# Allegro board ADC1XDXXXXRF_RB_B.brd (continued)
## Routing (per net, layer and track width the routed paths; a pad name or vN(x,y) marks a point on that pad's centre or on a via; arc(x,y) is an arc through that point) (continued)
FMC_DQD-7: length 142.1
  TOP w0.102: v1(119.71,97.74) U5.G7
  SIG3 w0.102: v1(119.71,97.74) 119.71,97.97 119.53,98.14 81.91,98.14 76.89,93.12 v3(76.89,92.79)
  BOTTOM w0.102: v3(76.89,92.79) 76.68,92.99 76.68,93.43 76.03,94.08 75.15,94.08 72.29,91.22 72.29,83.54 71.91,83.16 67.84,83.16 67.54,83.46 67.54,93.32 66.04,94.82 55.55,94.82 53.62,92.89 16.2,92.89 15.72,92.41 15.72,91.95 15.44,91.67 14.96,91.67 14.48,91.19 14.48,87.91 14.83,87.55 15.44,87.55 15.75,87.25 15.75,82.85 15.65,82.75 14.48,82.75 FMC.F11
FMC_DQD-8: length 142.1
  TOP w0.102: v1(118.71,101.75) 119.22,101.24 U5.D6
  SIG3 w0.102: v3(12.06,82.63) 12.6,82.09 46.27,82.09 46.38,82.19 46.38,82.53 46.6,82.75 46.97,82.75 47.19,82.53 47.19,82.19 47.29,82.09 47.49,82.09 47.59,82.19 47.59,82.53 47.81,82.75 48.19,82.75 48.41,82.53 48.41,82.19 48.51,82.09 48.71,82.09 48.81,82.19 48.81,82.53 49.03,82.75 49.41,82.75 49.63,82.53 49.63,82.19 49.73,82.09 49.93,82.09 50.03,82.19 50.03,82.53 50.25,82.75 50.62,82.75 50.85,82.53 50.85,82.19 50.95,82.09 51.15,82.09 51.25,82.19 51.25,82.53 51.47,82.75 51.84,82.75 52.06,82.53 52.06,82.19 52.17,82.09 52.37,82.09 52.47,82.19 52.47,82.53 52.69,82.75 53.06,82.75 53.28,82.53 53.28,82.19 53.39,82.09 53.59,82.09 53.69,82.19 53.69,82.53 53.91,82.75 54.28,82.75 54.5,82.53 54.5,82.19 54.6,82.09 54.81,82.09 54.91,82.19 54.91,82.53 55.13,82.75 55.5,82.75 55.72,82.53 55.72,82.19 55.82,82.09 56.03,82.09 56.13,82.19 56.13,82.53 56.35,82.75 56.72,82.75 56.94,82.53 56.94,82.19 57.04,82.09 57.25,82.09 57.35,82.19 57.35,82.53 57.57,82.75 57.94,82.75 58.16,82.53 58.16,82.19 58.26,82.09 58.47,82.09 58.57,82.19 58.57,82.53 58.79,82.75 59.16,82.75 59.38,82.53 59.38,82.19 59.48,82.09 59.68,82.09 59.79,82.19 59.79,82.56 60.01,82.78 60.38,82.78 60.6,82.56 60.6,82.19 60.7,82.09 61.16,82.09 69.6,90.53 69.6,91.74 69.49,91.84 69.16,91.84 68.94,92.06 68.94,92.43 69.16,92.65 69.49,92.65 69.6,92.75 69.6,92.96 69.49,93.06 69.16,93.06 68.94,93.28 68.94,93.65 69.16,93.87 69.49,93.87 69.6,93.97 69.6,94.17 69.49,94.28 69.16,94.28 68.94,94.5 68.94,94.87 69.16,95.09 69.49,95.09 69.6,95.19 69.6,95.39 69.49,95.5 69.16,95.5 68.94,95.72 68.94,96.09 69.16,96.31 69.49,96.31 69.6,96.41 69.6,96.61 69.49,96.71 69.16,96.71 68.94,96.94 68.94,97.31 69.16,97.53 69.49,97.53 69.6,97.63 69.6,97.83 69.49,97.93 69.16,97.93 68.94,98.15 68.94,98.53 69.16,98.75 69.49,98.75 69.6,98.85 69.6,99.05 69.49,99.15 69.16,99.15 68.94,99.37 68.94,99.75 69.16,99.97 69.49,99.97 69.6,100.07 69.6,101.25 69.89,101.55 112.98,101.55 113.17,101.36 119.04,101.36 119.2,101.52 119.2,101.6 119.05,101.75 118.71,101.75 v1(118.71,101.75)
  BOTTOM w0.102: FMC.E10 v3(12.06,82.63)
FMC_DQD-9: length 142.1
  TOP w0.102: U5.A5 v1(118.71,104.76)
  SIG3 w0.102: v3(63.02,91.52) 63.02,91.53 63.25,91.76 63.25,93.14 63.14,93.24 60.7,93.24 60.48,93.46 60.48,93.83 60.7,94.05 63.14,94.05 63.25,94.15 63.25,94.36 63.14,94.46 60.7,94.46 60.48,94.68 60.48,95.05 60.7,95.27 63.14,95.27 63.25,95.37 63.25,95.57 63.14,95.68 60.7,95.68 60.48,95.9 60.48,96.27 60.7,96.49 63.14,96.49 63.25,96.59 63.25,96.79 63.14,96.9 60.7,96.9 60.48,97.12 60.48,97.49 60.7,97.71 63.14,97.71 63.25,97.81 63.25,106.87 64.28,107.9 116.47,107.9 118.31,106.06 118.31,104.63 118.43,104.5 118.58,104.5 118.71,104.63 v1(118.71,104.76)
  BOTTOM w0.102: FMC.K14 19.05,86.66 19.15,86.56 52.7,86.56 57.15,91.01 63.12,91.01 63.22,91.11 63.22,91.31 v3(63.02,91.52)
FMC_DQD-10: length 142.2
  TOP w0.102: v1(116.71,103.76) 117.22,103.25 U5.B4
  SIG3 w0.102: v1(116.71,103.76) 117.31,104.36 117.31,105 115.68,106.63 65.04,106.63 64.52,106.1 64.52,91.14 59.28,85.9 53.39,85.9 53.28,86 53.28,87.43 53.06,87.66 52.69,87.66 52.47,87.43 52.47,86 52.37,85.9 52.17,85.9 52.06,86 52.06,87.43 51.84,87.66 51.47,87.66 51.25,87.43 51.25,86 51.15,85.9 50.95,85.9 50.85,86 50.85,87.43 50.62,87.66 50.25,87.66 50.03,87.43 50.03,86 49.93,85.9 49.73,85.9 49.63,86 49.63,87.43 49.41,87.66 49.03,87.66 48.81,87.43 48.81,86 48.71,85.9 48.51,85.9 48.41,86 48.41,87.43 48.19,87.66 47.81,87.66 47.59,87.43 47.59,86 47.49,85.9 47.29,85.9 47.19,86 47.19,87.43 46.97,87.66 46.6,87.66 46.38,87.43 46.38,86 46.27,85.9 46.07,85.9 45.97,86 45.97,87.43 45.75,87.66 45.38,87.66 45.16,87.43 45.16,86 45.05,85.9 18.95,85.9 v3(18.41,86.44)
  BOTTOM w0.102: FMC.J13 v3(18.41,86.44)
FMC_DQD-11: length 142.1
  TOP w0.102: v1(115.7,103.76) 116.22,103.25 U5.B3
  SIG3 w0.102: v1(115.7,103.76) 115.31,104.16 114.61,104.16 113.61,105.16 66.42,105.16 65.99,104.72 65.99,99.98 65.77,99.76 65.46,99.76 65.35,99.66 65.35,99.46 65.46,99.36 65.77,99.36 65.99,99.14 65.99,98.76 65.77,98.54 65.46,98.54 65.35,98.44 65.35,98.24 65.46,98.14 65.77,98.14 65.99,97.92 65.99,97.54 65.77,97.32 65.46,97.32 65.35,97.22 65.35,97.02 65.46,96.92 65.77,96.92 65.99,96.7 65.99,96.33 65.77,96.1 65.46,96.1 65.35,96 65.35,95.8 65.46,95.7 65.77,95.7 65.99,95.48 65.99,95.11 65.77,94.89 65.46,94.89 65.35,94.78 65.35,94.58 65.46,94.48 65.77,94.48 65.99,94.26 65.99,93.89 65.77,93.67 65.46,93.67 65.35,93.56 65.35,93.36 65.46,93.26 65.77,93.26 65.99,93.04 65.99,90.91 59.51,84.43 58.18,84.43 57.96,84.65 57.96,84.96 57.86,85.06 57.65,85.06 57.55,84.96 57.55,84.65 57.33,84.43 56.96,84.43 56.74,84.65 56.74,84.96 56.64,85.06 56.43,85.06 56.33,84.96 56.33,84.65 56.11,84.43 55.74,84.43 55.52,84.65 55.52,84.96 55.42,85.06 55.21,85.06 55.11,84.96 55.11,84.65 54.89,84.43 54.52,84.43 54.3,84.65 54.3,84.96 54.2,85.06 54,85.06 53.89,84.96 53.89,84.65 53.67,84.43 53.3,84.43 53.08,84.65 53.08,84.96 52.98,85.06 52.78,85.06 52.67,84.96 52.67,84.65 52.45,84.43 52.08,84.43 51.86,84.65 51.86,84.96 51.76,85.06 51.56,85.06 51.46,84.96 51.46,84.65 51.23,84.43 50.86,84.43 50.64,84.65 50.64,84.99 50.54,85.09 50.34,85.09 50.24,84.99 50.24,84.65 50.02,84.43 49.64,84.43 49.42,84.65 49.42,84.99 49.32,85.09 49.12,85.09 49.02,84.99 49.02,84.65 48.8,84.43 48.42,84.43 48.2,84.65 48.2,84.99 48.1,85.09 47.9,85.09 47.8,84.99 47.8,84.65 47.58,84.43 47.21,84.43 46.98,84.65 46.98,84.99 46.88,85.09 46.68,85.09 46.58,84.99 46.58,84.65 46.36,84.43 46,84.43 45.52,84.91 19.35,84.91 18.87,84.43 16.37,84.43 15.12,85.69 11.52,85.69 11.33,85.88 11.33,86.94 11.56,87.17 12.8,87.17 v3(13.34,87.71)
  BOTTOM w0.102: FMC.F14 v3(13.34,87.71)
FMC_ORI+: length 142.1
  TOP w0.102: v1(119.72,95.75) U5.J7
  SIG1 w0.102: v1(119.72,95.75) 119.32,96.14 119.32,99 117.97,100.36 115.27,100.36 103.06,112.57 55.59,112.57 55.49,112.67 55.49,113.9 55.27,114.12 54.9,114.12 54.68,113.9 54.68,112.67 54.58,112.57 54.38,112.57 54.27,112.67 54.27,113.9 54.05,114.12 53.68,114.12 53.46,113.9 53.46,112.67 53.36,112.57 53.16,112.57 53.05,112.67 53.05,113.9 52.83,114.12 52.46,114.12 52.24,113.9 52.24,112.67 52.14,112.57 51.94,112.57 51.84,112.67 51.84,113.93 51.62,114.15 51.24,114.15 51.02,113.93 51.02,112.67 50.92,112.57 50.72,112.57 50.62,112.67 50.62,113.93 50.4,114.15 50.02,114.15 49.8,113.93 49.8,112.67 49.7,112.57 49.5,112.57 49.4,112.67 49.4,113.93 49.18,114.15 48.8,114.15 48.58,113.93 48.58,112.67 48.48,112.57 48.28,112.57 48.18,112.67 48.18,113.93 47.96,114.15 47.59,114.15 47.37,113.93 47.37,112.67 47.26,112.57 47.06,112.57 46.96,112.67 46.96,113.93 46.74,114.15 46.37,114.15 46.15,113.93 46.15,112.67 46.04,112.57 14.22,112.57 14.07,112.73 14.07,113.48 14.23,113.64 16.61,113.64 v3(17.14,113.11)
  BOTTOM w0.102: FMC.H34 v3(17.14,113.11)
FMC_ORI-: length 142.1
  TOP w0.102: v1(118.72,95.75) U5.J6
  SIG1 w0.102: v1(118.72,95.75) 119.11,96.14 119.11,98.92 117.88,100.15 115.19,100.15 102.97,112.37 55.51,112.37 55.29,112.59 55.29,113.82 55.19,113.92 54.99,113.92 54.88,113.82 54.88,112.59 54.66,112.37 54.29,112.37 54.07,112.59 54.07,113.82 53.97,113.92 53.77,113.92 53.66,113.82 53.66,112.59 53.44,112.37 53.07,112.37 52.85,112.59 52.85,113.82 52.75,113.92 52.55,113.92 52.45,113.82 52.45,112.59 52.22,112.37 51.85,112.37 51.63,112.59 51.63,113.84 51.53,113.94 51.33,113.94 51.23,113.84 51.23,112.59 51.01,112.37 50.63,112.37 50.41,112.59 50.41,113.84 50.31,113.94 50.11,113.94 50.01,113.84 50.01,112.59 49.79,112.37 49.41,112.37 49.19,112.59 49.19,113.84 49.09,113.94 48.89,113.94 48.79,113.84 48.79,112.59 48.57,112.37 48.2,112.37 47.97,112.59 47.97,113.84 47.87,113.94 47.67,113.94 47.57,113.84 47.57,112.59 47.35,112.37 46.98,112.37 46.76,112.59 46.76,113.84 46.65,113.94 46.45,113.94 46.35,113.84 46.35,112.59 46.13,112.37 14.14,112.37 13.87,112.64 13.87,113.56 14.15,113.84 16.1,113.84 16.28,114.02 16.28,114.25 16.15,114.38 v3(15.88,114.38)
  BOTTOM w0.102: FMC.H35 v3(15.88,114.38)
FMC_ORQ+: length 142.1
  TOP w0.102: v1(120.71,96.74) U5.H8
  SIG1 w0.102: v1(120.71,96.74) 120.31,96.34 120.31,95.41 120.04,95.14 118.34,95.14 118.12,95.36 118.12,98.96 117.93,99.14 112.29,99.14 100.33,111.1 71.36,111.1 71.14,111.32 71.14,111.66 71.04,111.76 70.83,111.76 70.73,111.66 70.73,111.32 70.51,111.1 70.14,111.1 69.92,111.32 69.92,111.66 69.82,111.76 69.62,111.76 69.51,111.66 69.51,111.32 69.29,111.1 68.92,111.1 68.7,111.32 68.7,111.66 68.6,111.76 68.4,111.76 68.29,111.66 68.29,111.32 68.07,111.1 67.7,111.1 67.48,111.32 67.48,111.66 67.38,111.76 67.18,111.76 67.08,111.66 67.08,111.32 66.86,111.1 66.48,111.1 66.26,111.32 66.26,111.66 66.16,111.76 65.96,111.76 65.86,111.66 65.86,111.32 65.64,111.1 65.26,111.1 65.04,111.32 65.04,111.66 64.94,111.76 64.74,111.76 64.64,111.66 64.64,111.32 64.42,111.1 64.04,111.1 63.82,111.32 63.82,111.66 63.72,111.76 63.52,111.76 63.42,111.66 63.42,111.32 63.2,111.1 62.83,111.1 62.61,111.32 62.61,111.66 62.5,111.76 62.3,111.76 62.2,111.66 62.2,111.32 61.98,111.1 61.61,111.1 61.39,111.32 61.39,111.66 61.28,111.76 61.08,111.76 60.98,111.66 60.98,111.32 60.76,111.1 60.39,111.1 60.17,111.32 60.17,111.66 60.07,111.76 59.86,111.76 59.76,111.66 59.76,111.32 59.54,111.1 59.17,111.1 58.95,111.32 58.95,111.66 58.85,111.76 58.64,111.76 58.54,111.66 58.54,111.32 58.32,111.1 57.95,111.1 57.73,111.32 57.73,111.66 57.63,111.76 57.42,111.76 57.32,111.66 57.32,111.32 57.1,111.1 56.73,111.1 56.51,111.32 56.51,111.66 56.41,111.76 56.2,111.76 56.1,111.66 56.1,111.32 55.88,111.1 55.51,111.1 55.29,111.32 55.29,111.63 55.19,111.73 54.99,111.73 54.88,111.63 54.88,111.32 54.66,111.1 54.29,111.1 54.07,111.32 54.07,111.63 53.97,111.73 53.77,111.73 53.66,111.63 53.66,111.32 53.44,111.1 53.07,111.1 52.85,111.32 52.85,111.63 52.75,111.73 52.55,111.73 52.45,111.63 52.45,111.32 52.22,111.1 51.85,111.1 51.63,111.32 51.63,111.63 51.53,111.73 51.33,111.73 51.23,111.63 51.23,111.32 51.01,111.1 50.63,111.1 50.41,111.32 50.41,111.63 50.31,111.73 50.11,111.73 50.01,111.63 50.01,111.32 49.79,111.1 49.41,111.1 49.19,111.32 49.19,111.63 49.09,111.73 48.89,111.73 48.79,111.63 48.79,111.32 48.57,111.1 48.2,111.1 47.97,111.32 47.97,111.63 47.87,111.73 47.67,111.73 47.57,111.63 47.57,111.32 47.35,111.1 46.98,111.1 46.76,111.32 46.76,111.63 46.65,111.73 46.45,111.73 46.35,111.63 46.35,111.32 46.13,111.1 15.49,111.1 15.34,110.95 15.34,108.81 15.09,108.56 12.6,108.56 v3(12.06,108.03)
  BOTTOM w0.102: FMC.E30 v3(12.06,108.03)
FMC_ORQ-: length 142.1
  TOP w0.102: v1(119.71,96.74) U5.H7
  SIG1 w0.102: v3(12.06,109.3) 12.06,108.92 12.22,108.76 15,108.76 15.14,108.9 15.14,111.03 15.41,111.3 46.04,111.3 46.15,111.4 46.15,111.72 46.37,111.94 46.74,111.94 46.96,111.72 46.96,111.4 47.06,111.3 47.26,111.3 47.37,111.4 47.37,111.72 47.59,111.94 47.96,111.94 48.18,111.72 48.18,111.4 48.28,111.3 48.48,111.3 48.58,111.4 48.58,111.72 48.8,111.94 49.18,111.94 49.4,111.72 49.4,111.4 49.5,111.3 49.7,111.3 49.8,111.4 49.8,111.72 50.02,111.94 50.4,111.94 50.62,111.72 50.62,111.4 50.72,111.3 50.92,111.3 51.02,111.4 51.02,111.72 51.24,111.94 51.62,111.94 51.84,111.72 51.84,111.4 51.94,111.3 52.14,111.3 52.24,111.4 52.24,111.72 52.46,111.94 52.83,111.94 53.05,111.72 53.05,111.4 53.16,111.3 53.36,111.3 53.46,111.4 53.46,111.72 53.68,111.94 54.05,111.94 54.27,111.72 54.27,111.4 54.38,111.3 54.58,111.3 54.68,111.4 54.68,111.72 54.9,111.94 55.27,111.94 55.49,111.72 55.49,111.4 55.59,111.3 55.8,111.3 55.9,111.4 55.9,111.74 56.12,111.96 56.49,111.96 56.71,111.74 56.71,111.4 56.81,111.3 57.02,111.3 57.12,111.4 57.12,111.74 57.34,111.96 57.71,111.96 57.93,111.74 57.93,111.4 58.03,111.3 58.24,111.3 58.34,111.4 58.34,111.74 58.56,111.96 58.93,111.96 59.15,111.74 59.15,111.4 59.25,111.3 59.46,111.3 59.56,111.4 59.56,111.74 59.78,111.96 60.15,111.96 60.37,111.74 60.37,111.4 60.47,111.3 60.67,111.3 60.78,111.4 60.78,111.74 61,111.96 61.37,111.96 61.59,111.74 61.59,111.4 61.69,111.3 61.89,111.3 62,111.4 62,111.74 62.22,111.96 62.59,111.96 62.81,111.74 62.81,111.4 62.91,111.3 63.11,111.3 63.21,111.4 63.21,111.74 63.44,111.96 63.81,111.96 64.03,111.74 64.03,111.4 64.13,111.3 64.33,111.3 64.43,111.4 64.43,111.74 64.65,111.96 65.03,111.96 65.25,111.74 65.25,111.4 65.35,111.3 65.55,111.3 65.65,111.4 65.65,111.74 65.87,111.96 66.25,111.96 66.47,111.74 66.47,111.4 66.57,111.3 66.77,111.3 66.87,111.4 66.87,111.74 67.09,111.96 67.46,111.96 67.69,111.74 67.69,111.4 67.79,111.3 67.99,111.3 68.09,111.4 68.09,111.74 68.31,111.96 68.68,111.96 68.9,111.74 68.9,111.4 69.01,111.3 69.21,111.3 69.31,111.4 69.31,111.74 69.53,111.96 69.9,111.96 70.12,111.74 70.12,111.4 70.23,111.3 70.43,111.3 70.53,111.4 70.53,111.74 70.75,111.96 71.12,111.96 71.34,111.74 71.34,111.4 71.44,111.3 100.41,111.3 112.37,99.34 118.02,99.34 118.32,99.04 118.32,95.45 118.42,95.34 119.96,95.34 120.11,95.5 120.11,96.5 119.87,96.74 v1(119.71,96.74)
  BOTTOM w0.102: FMC.E31 v3(12.06,109.3)
FMC_PG_C2M: length 124.3
  TOP w0.102: U5.R5 118.2,90.24 v1(117.71,89.75)
  BOTTOM w0.152: FMC.D1 12.67,69.32 47.75,69.32 J155.1 50.72,66.34 76.83,66.34 84.02,73.53 84.02,82.75 90.47,89.2 109.42,89.2 R155.2 110.46,90.25 117.21,90.25 v1(117.71,89.75)
FMC_PG_M2C: length 123.5
  TOP w0.102: v1(118.71,89.75) 119.2,90.24 U5.R6
  BOTTOM w0.152: v1(118.71,89.75) 118.21,90.24 118.21,91.03 118.01,91.24 110.26,91.24 R156.1 109.55,91.24 90.35,91.24 83.24,84.12 83.24,74.5 76.35,67.61 J156.1 50.09,69.93 14.61,69.93 FMC.F1
FMC_RCOUT1+: length 142.1
  TOP w0.102: U5.U23 v1(135.72,87.74)
  SIG1 w0.102: v1(135.72,87.74) 135.72,87.32 136.12,86.92 136.12,86.57 135.69,86.14 131.48,86.14 130.48,87.14 119.53,87.14 119.31,86.92 119.31,86.43 119.02,86.14 101.95,86.14 94.77,93.32 62.85,93.32 62.63,93.54 62.63,93.73 62.53,93.83 62.33,93.83 62.22,93.73 62.22,93.54 62,93.32 61.63,93.32 61.41,93.54 61.41,93.73 61.31,93.83 61.11,93.83 61,93.73 61,93.54 60.78,93.32 60.41,93.32 60.19,93.54 60.19,93.73 60.09,93.83 59.89,93.83 59.79,93.73 59.79,93.54 59.57,93.32 59.19,93.32 58.97,93.54 58.97,93.73 58.87,93.83 58.67,93.83 58.57,93.73 58.57,93.54 58.35,93.32 57.97,93.32 57.75,93.54 57.75,93.73 57.65,93.83 57.45,93.83 57.35,93.73 57.35,93.54 57.13,93.32 56.76,93.32 56.53,93.54 56.53,93.73 56.43,93.83 56.23,93.83 56.13,93.73 56.13,93.54 55.91,93.32 55.54,93.32 55.32,93.54 55.32,93.73 55.21,93.83 55.01,93.83 54.91,93.73 54.91,93.54 54.69,93.32 54.32,93.32 54.1,93.54 54.1,93.75 53.99,93.85 53.79,93.85 53.69,93.75 53.69,93.54 53.47,93.32 53.1,93.32 52.88,93.54 52.88,93.75 52.78,93.85 52.57,93.85 52.47,93.75 52.47,93.54 52.25,93.32 51.88,93.32 51.66,93.54 51.66,93.75 51.56,93.85 51.35,93.85 51.25,93.75 51.25,93.54 51.03,93.32 50.66,93.32 50.44,93.54 50.44,93.75 50.34,93.85 50.13,93.85 50.03,93.75 50.03,93.54 49.81,93.32 49.44,93.32 49.22,93.54 49.22,93.75 49.12,93.85 48.91,93.85 48.81,93.75 48.81,93.54 48.59,93.32 48.22,93.32 48,93.54 48,93.75 47.9,93.85 47.7,93.85 47.59,93.75 47.59,93.54 47.37,93.32 47,93.32 46.78,93.54 46.78,93.75 46.68,93.85 46.48,93.85 46.37,93.75 46.37,93.54 46.15,93.32 11.33,93.32 v3(10.79,92.79)
  BOTTOM w0.102: FMC.C18 v3(10.79,92.79)
FMC_RCOUT1-: length 142
  TOP w0.102: U5.V23 v1(135.72,86.74)
  SIG1 w0.102: v3(9.53,94.06) 9.47,94.01 9.47,93.65 9.6,93.52 46.07,93.52 46.17,93.62 46.17,93.84 46.39,94.06 46.76,94.06 46.98,93.84 46.98,93.62 47.09,93.52 47.29,93.52 47.39,93.62 47.39,93.84 47.61,94.06 47.98,94.06 48.2,93.84 48.2,93.62 48.3,93.52 48.51,93.52 48.61,93.62 48.61,93.84 48.83,94.06 49.2,94.06 49.42,93.84 49.42,93.62 49.52,93.52 49.73,93.52 49.83,93.62 49.83,93.84 50.05,94.06 50.42,94.06 50.64,93.84 50.64,93.62 50.74,93.52 50.95,93.52 51.05,93.62 51.05,93.84 51.27,94.06 51.64,94.06 51.86,93.84 51.86,93.62 51.96,93.52 52.17,93.52 52.27,93.62 52.27,93.84 52.49,94.06 52.86,94.06 53.08,93.84 53.08,93.62 53.18,93.52 53.38,93.52 53.49,93.62 53.49,93.84 53.71,94.06 54.08,94.06 54.3,93.84 54.3,93.62 54.4,93.52 54.6,93.52 54.71,93.62 54.71,93.81 54.93,94.03 55.3,94.03 55.52,93.81 55.52,93.62 55.62,93.52 55.82,93.52 55.92,93.62 55.92,93.81 56.15,94.03 56.52,94.03 56.74,93.81 56.74,93.62 56.84,93.52 57.04,93.52 57.14,93.62 57.14,93.81 57.36,94.03 57.74,94.03 57.96,93.81 57.96,93.62 58.06,93.52 58.26,93.52 58.36,93.62 58.36,93.81 58.58,94.03 58.96,94.03 59.18,93.81 59.18,93.62 59.28,93.52 59.48,93.52 59.58,93.62 59.58,93.81 59.8,94.03 60.17,94.03 60.4,93.81 60.4,93.62 60.5,93.52 60.7,93.52 60.8,93.62 60.8,93.81 61.02,94.03 61.39,94.03 61.61,93.81 61.61,93.62 61.72,93.52 61.92,93.52 62.02,93.62 62.02,93.81 62.24,94.03 62.61,94.03 62.83,93.81 62.83,93.62 62.94,93.52 94.85,93.52 102.03,86.34 118.94,86.34 119.11,86.51 119.11,87.01 119.44,87.34 130.57,87.34 131.56,86.34 135.59,86.34 135.72,86.47 v1(135.72,86.74)
  BOTTOM w0.102: FMC.C19 v3(9.53,94.06)
FMC_RCOUT2+: length 142.1
  TOP w0.102: U5.U22 v1(134.72,87.74)
  SIG1 w0.102: v3(17.14,94.06) 17.14,94.39 17.35,94.59 46.15,94.59 46.37,94.81 46.37,95.05 46.48,95.15 46.68,95.15 46.78,95.05 46.78,94.81 47,94.59 47.37,94.59 47.59,94.81 47.59,95.05 47.7,95.15 47.9,95.15 48,95.05 48,94.81 48.22,94.59 48.59,94.59 48.81,94.81 48.81,95.05 48.91,95.15 49.12,95.15 49.22,95.05 49.22,94.81 49.44,94.59 49.81,94.59 50.03,94.81 50.03,95.05 50.13,95.15 50.34,95.15 50.44,95.05 50.44,94.81 50.66,94.59 51.03,94.59 51.25,94.81 51.25,95.05 51.35,95.15 51.56,95.15 51.66,95.05 51.66,94.81 51.88,94.59 52.25,94.59 52.47,94.81 52.47,95.05 52.57,95.15 52.78,95.15 52.88,95.05 52.88,94.81 53.1,94.59 53.47,94.59 53.69,94.81 53.69,95.05 53.79,95.15 53.99,95.15 54.1,95.05 54.1,94.81 54.32,94.59 54.69,94.59 54.91,94.81 54.91,95.05 55.01,95.15 55.21,95.15 55.32,95.05 55.32,94.81 55.54,94.59 55.91,94.59 56.13,94.81 56.13,95.05 56.23,95.15 56.43,95.15 56.53,95.05 56.53,94.81 56.76,94.59 57.13,94.59 57.35,94.81 57.35,95.05 57.45,95.15 57.65,95.15 57.75,95.05 57.75,94.81 57.97,94.59 58.35,94.59 58.57,94.81 58.57,95.05 58.67,95.15 58.87,95.15 58.97,95.05 58.97,94.81 59.19,94.59 59.57,94.59 59.79,94.81 59.79,95.05 59.89,95.15 60.09,95.15 60.19,95.05 60.19,94.81 60.41,94.59 60.78,94.59 61,94.81 61,95.05 61.11,95.15 61.31,95.15 61.41,95.05 61.41,94.81 61.63,94.59 62,94.59 62.22,94.81 62.22,95.05 62.33,95.15 62.53,95.15 62.63,95.05 62.63,94.81 62.85,94.59 63.22,94.59 63.44,94.81 63.44,95.05 63.54,95.15 63.75,95.15 63.85,95.05 63.85,94.81 64.07,94.59 64.44,94.59 64.66,94.81 64.66,95.05 64.76,95.15 64.97,95.15 65.07,95.05 65.07,94.81 65.29,94.59 65.66,94.59 65.88,94.81 65.88,95.05 65.98,95.15 66.19,95.15 66.29,95.05 66.29,94.81 66.51,94.59 66.88,94.59 67.1,94.81 67.1,95.05 67.2,95.15 67.41,95.15 67.51,95.05 67.51,94.81 67.73,94.59 68.1,94.59 68.32,94.81 68.32,95.05 68.42,95.15 68.62,95.15 68.73,95.05 68.73,94.81 68.95,94.59 69.32,94.59 69.54,94.81 69.54,95.05 69.64,95.15 69.84,95.15 69.95,95.05 69.95,94.81 70.17,94.59 70.54,94.59 70.76,94.81 70.76,95.02 70.86,95.12 71.06,95.12 71.16,95.02 71.16,94.81 71.39,94.59 71.76,94.59 71.98,94.81 71.98,95.02 72.08,95.12 72.28,95.12 72.38,95.02 72.38,94.81 72.6,94.59 72.98,94.59 73.2,94.81 73.2,95.02 73.3,95.12 73.5,95.12 73.6,95.02 73.6,94.81 73.82,94.59 74.2,94.59 74.42,94.81 74.42,95.02 74.52,95.12 74.72,95.12 74.82,95.02 74.82,94.81 75.04,94.59 75.41,94.59 75.64,94.81 75.64,95.02 75.74,95.12 75.94,95.12 76.04,95.02 76.04,94.81 76.26,94.59 96.92,94.59 104.37,87.14 117.99,87.14 118.32,87.47 118.32,87.9 118.56,88.14 131.9,88.14 132.72,87.33 133.88,87.33 134.3,87.74 v1(134.72,87.74)
  BOTTOM w0.102: FMC.H19 v3(17.14,94.06)
FMC_RCOUT2-: length 142.1
  TOP w0.102: U5.U21 v1(133.72,87.74)
  SIG1 w0.102: v1(133.72,87.74) 133.5,87.53 132.8,87.53 131.99,88.34 118.47,88.34 118.12,87.99 118.12,87.55 117.91,87.34 104.45,87.34 97,94.79 76.35,94.79 76.24,94.89 76.24,95.11 76.02,95.33 75.65,95.33 75.43,95.11 75.43,94.89 75.33,94.79 75.13,94.79 75.03,94.89 75.03,95.11 74.81,95.33 74.43,95.33 74.21,95.11 74.21,94.89 74.11,94.79 73.91,94.79 73.81,94.89 73.81,95.11 73.59,95.33 73.21,95.33 72.99,95.11 72.99,94.89 72.89,94.79 72.69,94.79 72.59,94.89 72.59,95.11 72.37,95.33 72,95.33 71.77,95.11 71.77,94.89 71.67,94.79 71.47,94.79 71.37,94.89 71.37,95.11 71.15,95.33 70.78,95.33 70.56,95.11 70.56,94.89 70.45,94.79 70.25,94.79 70.15,94.89 70.15,95.13 69.93,95.35 69.56,95.35 69.34,95.13 69.34,94.89 69.23,94.79 69.03,94.79 68.93,94.89 68.93,95.13 68.71,95.35 68.34,95.35 68.12,95.13 68.12,94.89 68.02,94.79 67.81,94.79 67.71,94.89 67.71,95.13 67.49,95.35 67.12,95.35 66.9,95.13 66.9,94.89 66.8,94.79 66.59,94.79 66.49,94.89 66.49,95.13 66.27,95.35 65.9,95.35 65.68,95.13 65.68,94.89 65.58,94.79 65.37,94.79 65.27,94.89 65.27,95.13 65.05,95.35 64.68,95.35 64.46,95.13 64.46,94.89 64.36,94.79 64.15,94.79 64.05,94.89 64.05,95.13 63.83,95.35 63.46,95.35 63.24,95.13 63.24,94.89 63.14,94.79 62.94,94.79 62.83,94.89 62.83,95.13 62.61,95.35 62.24,95.35 62.02,95.13 62.02,94.89 61.92,94.79 61.72,94.79 61.61,94.89 61.61,95.13 61.39,95.35 61.02,95.35 60.8,95.13 60.8,94.89 60.7,94.79 60.5,94.79 60.4,94.89 60.4,95.13 60.17,95.35 59.8,95.35 59.58,95.13 59.58,94.89 59.48,94.79 59.28,94.79 59.18,94.89 59.18,95.13 58.96,95.35 58.58,95.35 58.36,95.13 58.36,94.89 58.26,94.79 58.06,94.79 57.96,94.89 57.96,95.13 57.74,95.35 57.36,95.35 57.14,95.13 57.14,94.89 57.04,94.79 56.84,94.79 56.74,94.89 56.74,95.13 56.52,95.35 56.15,95.35 55.92,95.13 55.92,94.89 55.82,94.79 55.62,94.79 55.52,94.89 55.52,95.13 55.3,95.35 54.93,95.35 54.71,95.13 54.71,94.89 54.6,94.79 54.4,94.79 54.3,94.89 54.3,95.13 54.08,95.35 53.71,95.35 53.49,95.13 53.49,94.89 53.38,94.79 53.18,94.79 53.08,94.89 53.08,95.13 52.86,95.35 52.49,95.35 52.27,95.13 52.27,94.89 52.17,94.79 51.96,94.79 51.86,94.89 51.86,95.13 51.64,95.35 51.27,95.35 51.05,95.13 51.05,94.89 50.95,94.79 50.74,94.79 50.64,94.89 50.64,95.13 50.42,95.35 50.05,95.35 49.83,95.13 49.83,94.89 49.73,94.79 49.52,94.79 49.42,94.89 49.42,95.13 49.2,95.35 48.83,95.35 48.61,95.13 48.61,94.89 48.51,94.79 48.3,94.79 48.2,94.89 48.2,95.13 47.98,95.35 47.61,95.35 47.39,95.13 47.39,94.89 47.29,94.79 47.09,94.79 46.98,94.89 46.98,95.13 46.76,95.35 46.39,95.35 46.17,95.13 46.17,94.89 46.07,94.79 16.41,94.79 v3(15.88,95.33)
  BOTTOM w0.102: FMC.H20 v3(15.88,95.33)
FPGA_RESET: length 56.4
  TOP w0.102: 121.22,78.75 U5.AF8
  TOP w0.14: 121.22,77.6 121.22,73.2 117.31,69.29 117.31,39.78 112.79,35.26 R15.1 R16.2
  TOP w0.152: 121.22,77.6 121.22,78.75
FSR: length 63.2
  TOP w0.14: R27.2 164.98,144 166.25,145.27 J4.14
  SIG3 w0.152: J4.14 167.61,143.91 167.61,140.03 170.27,137.38 190.89,137.38 193.38,134.89 193.38,117.23 v1(193.37,117.23)
  BOTTOM w0.14: v1(193.37,117.23) 193.38,117.23 196.53,114.07 R2.1
IFCLK: length 88.4
  TOP w0.102: U5.AC10 123.22,82.25 v1(122.71,81.74)
  TOP w0.14: v1(84.66,28.27) U2.32
  SIG1 w0.152: v1(116.18,31.94) 116.18,59.44 123.22,66.48 123.22,81.23 122.71,81.74 v1(122.71,81.74)
  SIG3 w0.152: v1(84.66,28.27) 88.33,31.94 v1(116.18,31.94)
JP_1: length 75.4
  TOP w0.102: v1(127.71,81.74) 127.22,82.23 U5.AC14
  TOP w0.203: R33.2 J18.1
  SIG1 w0.152: v1(131.86,65.45) v1(145.76,65.45)
  SIG2 w0.152: v1(131.86,65.45) 127.22,70.09 127.22,81.25 127.71,81.74 v1(127.71,81.74) ; J18.1 145.76,28.33 v1(145.76,65.45)
JP_2: length 70.6
  TOP w0.102: v1(127.71,80.74) 127.22,81.23 U5.AD14
  TOP w0.203: R37.2 J18.3
  SIG1 w0.152: v1(143.3,64.82) v1(133.36,64.82)
  SIG2 w0.152: J18.3 143.3,28.25 v1(143.3,64.82) ; v1(133.36,64.82) 128.22,69.95 128.22,80.24 127.72,80.74 v1(127.71,80.74)
JP_3: length 77.8
  TOP w0.102: v1(124.71,83.74) 125.21,84.24 U5.AA12
  TOP w0.203: R36.2 J18.5
  SIG1 w0.152: v1(123.84,60.9) 123.84,43.55 124.97,42.42 v1(124.97,30.55)
  SIG3 w0.152: v1(124.97,30.55) 138.47,30.55 J18.5 ; v1(124.71,83.74) 124.71,83.74 125.2,83.25 125.2,81.45 126.14,80.52 126.14,67.51 123.84,65.21 v1(123.84,60.9)
JP_4: length 79
  TOP w0.102: U5.AA11 124.21,84.24 v1(123.71,83.74)
  TOP w0.203: R35.2 J18.7
  SIG1 w0.152: v1(121.82,59.02) v1(121.82,29.45)
  SIG3 w0.152: v1(123.71,83.74) 124.21,83.25 124.21,81.48 125.22,80.47 125.22,67.84 121.82,64.44 v1(121.82,59.02) ; J18.7 137.02,29.45 v1(121.82,29.45)
JP_5: length 63.2
  TOP w0.102: v1(129.72,81.74) 129.22,82.24 U5.AC16
  TOP w0.203: R32.2 J18.9
  SIG2 w0.152: J18.9 138.19,29.23 138.19,67.84 130.22,75.82 130.22,81.23 v1(129.72,81.74)
LED_ADC_CAL: length 108
  TOP w0.102: v1(125.71,79.74) 125.22,80.23 U5.AE12
  TOP w0.14: v1(183.51,38.8) 184.41,37.9 ADC_CALIBRATION.2
  SIG1 w0.152: v1(125.71,79.74) 126.21,79.24 126.21,76.43 130.15,72.49 152.69,72.49 157.12,68.06 v1(183.51,68.06)
  SIG3 w0.152: v1(183.51,68.06) v1(183.51,38.8)
LED_ADC_PWR: length 105.1
  TOP w0.102: 125.22,78.74 U5.AF12
  TOP w0.14: v1(125.71,76.34) 125.22,76.83 125.22,78.74 ; ADC_POWER.2 183.27,39.93 v1(182.75,40.45)
  SIG1 w0.152: v1(125.71,76.34) 130.09,71.96 152.21,71.96 156.87,67.3 v1(182.75,67.3)
  SIG3 w0.152: v1(182.75,67.3) v1(182.75,40.45)
LED_DCLK_LOCKED: length 102
  TOP w0.102: 123.22,78.77 U5.AF10
  TOP w0.14: 123.22,78.77 123.22,72.4 v1(123.71,71.91) ; v1(180.47,47.44) 181.85,46.06 DCLK_LOCKED.2
  SIG1 w0.152: v1(180.47,65.41) 155.64,65.41 153.84,67.21 128.41,67.21 v1(123.71,71.91)
  SIG3 w0.152: v1(180.47,65.41) v1(180.47,47.44)
LED_ECM_ENA: length 121.2
  TOP w0.102: U5.AD8 121.22,81.21 v1(120.75,80.74)
  TOP w0.14: ECM_ENABLED.2 v1(181.23,31.81)
  SIG1 w0.152: v1(181.23,66.08) 155.9,66.08 154.13,67.84 128.85,67.84 123.7,72.99 v1(123.7,74.35)
  SIG3 w0.152: v1(181.23,31.81) v1(181.23,66.08) ; v1(120.71,76.49) 120.57,76.63 120.56,76.63 120.21,76.98 120.21,80.2 v1(120.75,80.74)
  BOTTOM w0.14: v1(123.7,74.35) 122.53,74.35 120.71,76.17 v1(120.71,76.49)
LED_FPGA_OPER: length 115.2
  TOP w0.102: 124.22,78.76 U5.AF11
  TOP w0.14: 124.22,78.76 124.22,71.53 v1(123.71,71.02) ; FPGA_OPERATIONAL.2 v1(179.71,33.84)
  SIG1 w0.152: v1(179.71,64.72) 155.25,64.72 153.32,66.64 128.09,66.64 v1(123.71,71.02)
  SIG3 w0.152: v1(179.71,33.84) 179.71,41.54 179.71,41.55 179.71,42.39 179.71,42.39 v1(179.71,64.72)
LED_OVERRANGE_I: length 108.8
  TOP w0.102: v1(130.72,82.74) 130.22,83.24 U5.AB17
  TOP w0.14: v1(184.28,36.98) 185.39,35.87 OVER-RANGE_I-CH.2
  SIG1 w0.152: v1(134.61,73) 153.28,73 157.47,68.81 v1(184.28,68.81)
  SIG2 w0.152: v1(134.61,73) 134.61,74.47 132.22,76.86 132.22,81.99 131.98,82.23 131.24,82.23 130.73,82.74 v1(130.72,82.74)
  SIG3 w0.152: v1(184.28,68.81) v1(184.28,36.98)
LED_OVERRANGE_Q: length 99
  TOP w0.102: U5.AC17 130.22,82.24 v1(130.72,81.74)
  TOP w0.14: v1(187.17,45.03) 188.21,44 OVER-RANGE_Q-CH.2
  SIG1 w0.152: v1(131.22,75.51) 132.2,74.53 157.01,74.53 162.09,69.45 v1(185.06,69.45)
  SIG2 w0.152: v1(130.72,81.74) 130.72,81.74 131.22,81.24 v1(131.22,75.51)
  SIG3 w0.152: v1(187.17,45.03) 187.17,67.35 v1(185.06,69.45)
LED_RCOUT_ENA: length 123.9
  TOP w0.102: U5.AC8 121.21,82.25 v1(120.71,81.74)
  TOP w0.14: RCOUT1/2_ENABLED.2 v1(181.99,29.78)
  SIG1 w0.152: v1(181.99,66.74) 156.33,66.74 154.6,68.47 129.11,68.47 124.26,73.33 124.26,74.56 v1(123.7,75.13)
  SIG2 w0.152: v1(120.71,81.74) 121.22,81.23 121.22,77.87 v1(120.7,77.36)
  SIG3 w0.152: v1(181.99,66.74) v1(181.99,29.78)
  BOTTOM w0.14: v1(123.7,75.13) 121.47,77.36 v1(120.7,77.36)
LED_TRIGGER: length 111.9
  TOP w0.102: v1(122.71,82.74) 123.22,83.25 U5.AB10
  TOP w0.14: v1(178.94,41.97) TRIGGER_ARMED.2
  SIG1 w0.152: v1(123.71,70.21) 127.77,66.15 152.72,66.15 154.85,64.01 v1(178.94,64.01)
  SIG3 w0.152: v1(178.94,64.01) v1(178.94,41.97) ; v1(122.71,82.74) 122.2,82.23 122.2,71.72 v1(123.71,70.21)
LOAD_STATE: length 52.4
  TOP w0.102: U5.AE7 120.22,80.24 119.81,79.83
  TOP w0.14: v1(93.7,76.11) R14.2 ; v1(119.74,76.11) 119.81,76.18 119.81,79.83
  SIG3 w0.152: v1(119.74,76.11) v1(93.7,76.11)
NDM: length 166.2
  TOP w0.102: 134.22,78.74 U5.AF21
  TOP w0.14: v1(194.16,78.61) 183.41,78.61 176.79,71.98 140.88,71.98 134.22,78.64 134.22,78.74
  SIG3 w0.152: J4.26 157.36,144.01 157.36,141.52 164.72,134.15 186.91,134.15 187.86,133.2 187.86,115.26 190.47,112.65 193.37,112.65 195.43,110.58 195.43,79.88 v1(194.16,78.61)
  BOTTOM w0.14: v1(194.16,78.61) R127.1
ORI+: length 66
  TOP w0.102: U5.J26 139.22,96.25 v1(139.73,96.75) ; U1.K17 178.92,96.16 v1(178.35,95.6)
  SIG2 w0.102: v1(139.73,96.75) 139.94,96.54 151.73,96.54 152.04,96.85 152.04,99.26 152.52,99.75 162.11,99.75 162.22,99.85 162.22,101.36 162.44,101.58 162.81,101.58 163.03,101.36 163.03,99.85 163.13,99.75 163.33,99.75 163.43,99.85 163.43,101.36 163.65,101.58 164.03,101.58 164.25,101.36 164.25,99.85 164.35,99.75 164.55,99.75 164.65,99.85 164.65,101.36 164.87,101.58 165.25,101.58 165.47,101.36 165.47,99.85 165.57,99.75 165.77,99.75 165.87,99.85 165.87,101.36 166.09,101.58 166.46,101.58 166.69,101.36 166.69,99.85 166.79,99.75 166.99,99.75 167.09,99.85 167.09,101.36 167.31,101.58 167.68,101.58 167.9,101.36 167.9,99.85 168.01,99.75 168.21,99.75 168.31,99.85 168.31,101.36 168.53,101.58 168.9,101.58 169.12,101.36 169.12,99.85 169.23,99.75 172.95,99.75 173.41,99.28 173.41,96.59 173.72,96.28 177,96.28 177.27,96.01 177.28,96.01 177.69,95.6 v1(178.35,95.6)
ORI-: length 65.9
  TOP w0.102: v1(138.73,96.75) 138.22,96.25 U5.J25 ; v1(177.07,95.59) 177.64,96.16 U1.K18
  SIG2 w0.102: v1(177.07,95.59) 177.07,95.93 176.92,96.08 173.64,96.08 173.21,96.51 173.21,99.2 172.87,99.54 169.14,99.54 168.92,99.76 168.92,101.27 168.82,101.37 168.62,101.37 168.51,101.27 168.51,99.76 168.29,99.54 167.92,99.54 167.7,99.76 167.7,101.27 167.6,101.37 167.4,101.37 167.3,101.27 167.3,99.76 167.07,99.54 166.7,99.54 166.48,99.76 166.48,101.27 166.38,101.37 166.18,101.37 166.08,101.27 166.08,99.76 165.86,99.54 165.48,99.54 165.26,99.76 165.26,101.27 165.16,101.37 164.96,101.37 164.86,101.27 164.86,99.76 164.64,99.54 164.26,99.54 164.04,99.76 164.04,101.27 163.94,101.37 163.74,101.37 163.64,101.27 163.64,99.76 163.42,99.54 163.05,99.54 162.82,99.76 162.82,101.27 162.72,101.37 162.52,101.37 162.42,101.27 162.42,99.76 162.2,99.54 152.61,99.54 152.25,99.18 152.25,96.77 151.81,96.33 139.13,96.33 138.73,96.74 v1(138.73,96.75)
ORQ+: length 66
  TOP w0.102: U1.L17 178.92,97.43 v1(178.29,96.81) ; U5.H26 v1(139.73,97.75)
  SIG1 w0.102: v1(178.29,96.81) 177.59,96.81 177.23,96.45 177.23,96.45 176.94,96.16 174.41,96.16 174.18,96.38 174.18,96.85 174.08,96.95 173.88,96.95 173.78,96.85 173.78,96.38 173.56,96.16 173.19,96.16 172.97,96.38 172.97,96.85 172.86,96.95 172.66,96.95 172.56,96.85 172.56,96.38 172.34,96.16 171.97,96.16 171.75,96.38 171.75,96.85 171.64,96.95 171.44,96.95 171.34,96.85 171.34,96.38 171.12,96.16 170.75,96.16 170.53,96.38 170.53,96.85 170.43,96.95 170.22,96.95 170.12,96.85 170.12,96.38 169.9,96.16 169.53,96.16 169.31,96.38 169.31,96.85 169.21,96.95 169,96.95 168.85,96.79 168.85,94.83 168.63,94.61 161.02,94.61 160.6,95.02 160.6,102.09 160.4,102.29 158.5,102.29 158.4,102.18 158.4,101.48 158.18,101.26 157.81,101.26 157.58,101.48 157.58,102.18 157.48,102.29 157.28,102.29 157.18,102.18 157.18,101.48 156.96,101.26 156.59,101.26 156.37,101.48 156.37,102.18 156.26,102.29 156.06,102.29 155.96,102.18 155.96,101.48 155.74,101.26 155.37,101.26 155.15,101.48 155.15,102.18 155.04,102.29 154.69,102.29 154.47,102.51 154.47,102.96 154.37,103.06 154.16,103.06 154.06,102.96 154.06,102.51 153.84,102.29 153.05,102.29 152.94,102.18 152.94,98.13 152.42,97.61 140.54,97.61 140.2,97.95 139.92,97.95 v1(139.73,97.75)
ORQ-: length 65.9
  TOP w0.102: v1(138.73,97.75) 138.22,97.25 U5.H25 ; U1.L18 v1(177.03,96.81)
  SIG1 w0.102: v1(177.03,96.81) 177.03,96.53 176.86,96.36 174.49,96.36 174.39,96.46 174.39,96.93 174.17,97.15 173.8,97.15 173.58,96.93 173.58,96.46 173.47,96.36 173.27,96.36 173.17,96.46 173.17,96.93 172.95,97.15 172.58,97.15 172.36,96.93 172.36,96.46 172.25,96.36 172.05,96.36 171.95,96.46 171.95,96.93 171.73,97.15 171.36,97.15 171.14,96.93 171.14,96.46 171.04,96.36 170.83,96.36 170.73,96.46 170.73,96.93 170.51,97.15 170.14,97.15 169.92,96.93 169.92,96.46 169.82,96.36 169.61,96.36 169.51,96.46 169.51,96.93 169.29,97.15 168.92,97.15 168.65,96.88 168.65,94.91 168.55,94.81 161.1,94.81 160.8,95.11 160.8,102.17 160.49,102.49 158.41,102.49 158.19,102.27 158.19,101.57 158.09,101.47 157.89,101.47 157.79,101.57 157.79,102.27 157.57,102.49 157.2,102.49 156.98,102.27 156.98,101.57 156.87,101.47 156.67,101.47 156.57,101.57 156.57,102.27 156.35,102.49 155.98,102.49 155.76,102.27 155.76,101.57 155.65,101.47 155.45,101.47 155.35,101.57 155.35,102.27 155.13,102.49 154.77,102.49 154.67,102.59 154.67,103.05 154.45,103.27 154.08,103.27 153.86,103.05 153.86,102.59 153.76,102.49 152.96,102.49 152.74,102.27 152.74,98.21 152.34,97.81 140.63,97.81 140.29,98.15 139.13,98.15 v1(138.73,97.75)
PDI: length 66.8
  TOP w0.14: J4.2 176.41,145.27 175.14,144 R44.2
  SIG3 w0.152: v1(201.68,104.39) 201.68,112.48 198.42,115.73 198.42,134.9 192.46,140.86 178.74,140.86 177.99,141.6 177.99,143.69 J4.2
  BOTTOM w0.152: v1(201.68,104.39) 201.64,104.36 R9.1
PDQ: length 66
  TOP w0.14: J4.5 172.6,144.01 R45.2
  SIG3 w0.152: v1(200.6,106.93) 200.6,111.51 197.55,114.56 197.55,134.56 192.12,139.99 176.43,139.99 175.14,141.27 175.14,144.01 J4.5
  BOTTOM w0.14: R25.1 200.41,105.78 200.6,105.97 v1(200.6,106.93)
PKTEND: length 59.9
  TOP w0.102: U5.AE9 122.22,80.23 121.71,79.72
  TOP w0.14: v1(121.71,75.92) 121.71,79.72 ; v1(102.34,38.27) U2.91
  SIG1 w0.152: v1(113.16,38.27) 113.16,56.13 114.85,57.82 114.85,69.06 v1(121.71,75.92)
  SIG3 w0.152: v1(113.16,38.27) v1(102.34,38.27)
PLL_CE: length 86.3
  TOP w0.102: U5.C17 v1(129.72,102.75)
  TOP w0.14: TP20.1 177.76,152.3 J162.1
  SIG1 w0.152: v1(154.06,149.83) 152.02,147.78 152.02,146.48 130.2,124.66 130.2,106.96 129.24,105.99 129.24,103.23 v1(129.72,102.75)
  BOTTOM w0.14: TP20.1 175.29,149.83 v1(154.06,149.83)
PLL_LD: length 117.7
  TOP w0.102: U5.H5 v1(117.72,96.74)
  TOP w0.14: TP16.1 177.76,162.46 J158.1
  SIG3 w0.14: TP16.1 175.42,160.12
  SIG3 w0.152: 175.42,160.12 140.63,160.12 v1(120.22,139.71)
  BOTTOM w0.152: v1(117.72,96.74) 118.2,97.23 119.98,97.23 120.22,97.46 120.22,98.93 119.81,99.34 119.81,99.95 119.2,100.56 119.2,102.54 118.21,103.53 118.21,116.89 120.22,118.9 v1(120.22,139.71)
PLL_LE: length 104
  TOP w0.102: U5.D17 v1(129.72,101.74)
  TOP w0.14: J161.1 177.76,154.84 TP19.1
  SIG2 w0.152: v1(129.72,101.74) 129.23,102.23 129.23,113.9 128.68,114.45 v1(128.68,150.36)
  BOTTOM w0.14: TP19.1 173.28,150.36 v1(128.68,150.36)
PLL_SCLK: length 116.6
  TOP w0.102: v1(121.71,97.74) U5.G9
  TOP w0.14: J160.1 177.76,157.38 TP18.1
  SIG1 w0.152: v1(121.22,150.91) 121.22,98.24 v1(121.71,97.74)
  BOTTOM w0.14: v1(121.22,150.91) 171.29,150.91 TP18.1
PLL_SDATA: length 117.1
  TOP w0.102: v1(122.71,97.74) U5.G10
  TOP w0.14: TP17.1 177.76,159.92 J159.1
  SIG1 w0.152: v1(122.21,151.55) 122.21,98.25 v1(122.71,97.74)
  BOTTOM w0.14: v1(122.21,151.55) 169.39,151.55 TP17.1
PROGRAMB: length 198.2
  TOP w0.102: U5.H15 128.21,97.24 v1(127.71,96.75)
  TOP w0.14: v1(130.33,44.11) 141.26,44.11 142.33,45.19 R85.2 149.24,45.19 150.08,44.35 U14.6 ; U2.76 107.88,30.77 108.32,31.2 v1(129.2,31.2)
  SIG2 w0.152: v1(126.74,107.33) 126.74,112.93 v1(127.18,113.37)
  SIG3 w0.152: v1(129.2,31.2) 129.2,42.98 v1(130.33,44.11) ; v1(127.18,113.37) 129.35,113.37 131.5,115.51 v1(151.46,115.51) ; v1(126.74,107.33) 127.22,106.85 127.22,97.24 127.71,96.75 v1(127.71,96.75)
  BOTTOM w0.14: v1(151.46,115.51) 151.46,54.92 146.84,50.3 136.52,50.3 v1(130.33,44.11)
RCLK+: length 26.1
  TOP w0.102: R145.1 177.37,123.51 181.75,123.51 194.91,110.35 194.91,108.51 195.05,108.37 195.22,108.37 195.43,108.58 U1.Y4
RCLK+_IN: length 19.6
  TOP w0.102: R145.2 175.84,123.51 169.36,123.51 166.17,126.7 166.17,128.48 166.27,128.58 RCLK+.1
RCLK-: length 25.9
  TOP w0.102: R147.1 177.37,123.26 181.65,123.26 194.66,110.25 194.66,108.09 U1.W5
RCLK-_IN: length 19.6
  TOP w0.102: RCLK-.1 165.81,128.58 165.91,128.48 165.91,126.59 169.25,123.26 175.84,123.26 R147.2
RCOUT1+: length 52.2
  TOP w0.102: U5.B17 v1(130.72,102.75)
  SIG1 w0.102: v1(166.27,115.67) 164.34,115.67 163.5,114.83 150.94,114.83 150.84,114.94 150.84,115.27 150.62,115.49 150.25,115.49 150.03,115.27 150.03,114.94 149.93,114.83 149.72,114.83 149.62,114.94 149.62,115.32 149.4,115.54 149.03,115.54 148.81,115.32 148.81,114.94 148.71,114.83 148.5,114.83 148.4,114.94 148.4,115.32 148.18,115.54 147.81,115.54 147.59,115.32 147.59,114.94 147.49,114.83 147.28,114.83 147.18,114.94 147.18,115.35 146.96,115.57 146.59,115.57 146.37,115.35 146.37,114.94 146.27,114.83 146.06,114.83 145.96,114.94 145.96,115.35 145.74,115.57 145.37,115.57 145.15,115.35 145.15,114.94 145.05,114.83 144.85,114.83 144.74,114.94 144.74,115.35 144.52,115.57 144.15,115.57 143.93,115.35 143.93,114.94 143.83,114.83 143.63,114.83 143.52,114.94 143.52,115.32 143.3,115.54 142.93,115.54 142.71,115.32 142.71,114.94 142.61,114.83 142.41,114.83 142.31,114.94 142.31,115.32 142.08,115.54 141.71,115.54 141.49,115.32 141.49,114.94 141.39,114.83 139.9,114.83 130.15,105.08 130.15,103.32 v1(130.72,102.75)
RCOUT1+_OUT: length 26.4
  TOP w0.102: R160.3 163.25,115.37 161.8,115.37 150.24,126.92 148.56,126.92 148.46,127.03 RCOUT1+.1
RCOUT1-: length 52.2
  TOP w0.102: U5.A17 v1(130.72,103.75)
  SIG1 w0.102: v1(166.27,113.79) 164.34,113.79 163.5,114.63 150.86,114.63 150.64,114.85 150.64,115.19 150.53,115.29 150.33,115.29 150.23,115.19 150.23,114.85 150.01,114.63 149.64,114.63 149.42,114.85 149.42,115.24 149.32,115.34 149.11,115.34 149.01,115.24 149.01,114.85 148.79,114.63 148.42,114.63 148.2,114.85 148.2,115.24 148.1,115.34 147.89,115.34 147.79,115.24 147.79,114.85 147.57,114.63 147.2,114.63 146.98,114.85 146.98,115.27 146.88,115.37 146.67,115.37 146.57,115.27 146.57,114.85 146.35,114.63 145.98,114.63 145.76,114.85 145.76,115.27 145.66,115.37 145.45,115.37 145.35,115.27 145.35,114.85 145.13,114.63 144.76,114.63 144.54,114.85 144.54,115.27 144.44,115.37 144.24,115.37 144.13,115.27 144.13,114.85 143.91,114.63 143.54,114.63 143.32,114.85 143.32,115.24 143.22,115.34 143.02,115.34 142.91,115.24 142.91,114.85 142.69,114.63 142.32,114.63 142.1,114.85 142.1,115.24 142,115.34 141.8,115.34 141.7,115.24 141.7,114.85 141.47,114.63 139.99,114.63 130.35,105 130.35,104.79 130.45,104.7 131.09,104.7 131.17,104.62 131.17,104.48 131.09,104.41 130.44,104.41 130.35,104.32 130.35,104.11 v1(130.72,103.75)
RCOUT1-_OUT: length 26.4
  TOP w0.102: RCOUT1-.1 148.46,126.57 148.56,126.67 150.14,126.67 161.69,115.11 162.2,115.11 163.53,113.79 R159.3
RCOUT1N: length 35.6
  TOP w0.102: R159.2 v1(164.85,114.35) ; v1(193.47,105.63) 192.89,105.05 U1.U6
  SIG1 w0.102: v1(164.85,114.35) 165.13,114.63 186.56,114.63 191.52,109.68 191.52,107.87 191.84,107.54 192.66,107.54 192.89,107.31 192.89,106.22 v1(193.47,105.63)
RCOUT1P: length 35.6
  TOP w0.102: R160.2 v1(164.85,115.11) ; v1(193.52,109.51) 194.16,108.87 U1.Y5
  SIG1 w0.102: v1(164.85,115.11) 165.13,114.83 186.65,114.83 191.72,109.76 191.72,107.95 191.92,107.75 192.71,107.75 192.89,107.92 192.89,108.88 v1(193.52,109.51)
RCOUT2+: length 89.5
  TOP w0.102: v1(192.24,105.66) 192.24,105.68 U1.V6 ; v1(126.72,102.75) U5.C13
  SIG2 w0.102: J5.1 133.07,111.07 133.17,110.97 136.52,110.97 138.68,113.13 188.28,113.13 191.75,109.66 191.75,107.21 191.75,107.21 191.75,106.15 v1(192.24,105.66)
  SIG3 w0.102: J5.1 132.94,112.01 131.9,110.97 125.7,110.97 122.71,107.98 122.71,104.32 123.14,103.89 123.14,103.28 124.64,101.78 126.04,101.78 126.37,102.11 126.37,102.4 v1(126.72,102.75)
RCOUT2-: length 89.5
  TOP w0.102: v1(190.97,105.68) 191,105.68 191.65,106.32 U1.V7 ; v1(125.72,102.75) U5.C12
  SIG2 w0.102: J5.2 133.07,110.67 133.17,110.77 136.6,110.77 138.76,112.93 188.19,112.93 191.55,109.57 191.55,107.13 191.55,107.13 191.55,107.03 191.55,107.03 191.55,106.27 190.96,105.69 190.97,105.68 v1(190.97,105.68)
  SIG3 w0.102: J5.2 133.07,110.67 132.97,110.77 125.78,110.77 122.91,107.9 122.91,104.4 123.34,103.97 123.34,103.38 124.74,101.98 125.96,101.98 126.17,102.19 126.17,102.56 125.98,102.75 v1(125.72,102.75)
RD_N: length 92.8
  TOP w0.102: v1(120.71,84.74) 120.72,84.74 U5.Y8
  TOP w0.152: v1(85.23,26.39) U2.40
  SIG1 w0.152: v1(91.31,82.3) 91.31,60.99 88.83,58.51 88.83,29.99 v1(85.23,26.39)
  BOTTOM w0.152: v1(91.31,82.3) 94.25,85.24 120.21,85.24 v1(120.71,84.74)
RXD0: length 29
  TOP w0.14: U2.51 90.73,20.24 93.14,17.83 103.57,17.83 J25.4
RXD1: length 34.2
  TOP w0.14: J25.3 115.84,10.68 115.84,13.18 109.97,19.05 93.65,19.05 91.73,20.97 U2.53
SCL_FROM_CY: length 262.2
  TOP w0.14: U2.36 81.56,26.27 80.54,25.25 80.54,21.03 90.2,11.38 v1(90.2,9.53) ; U8.13 v1(159.46,56.07)
  TOP w0.152: U4.6 v1(94.39,9.53) R19.1
  SIG2 w0.152: J15.8 143.33,154.94 143.33,163.96 144.59,165.22 J17.8 ; v1(159.46,56.07) 160.66,54.87 160.66,27.38 137.46,4.19 109.02,4.19 105.11,8.1 95.81,8.1 v1(94.39,9.53) v1(90.2,9.53) ; v1(144.61,125.33) 145.22,124.71 153.26,124.71 v1(162.03,115.94)
  SIG3 w0.14: J15.8 v1(144.61,125.33)
  BOTTOM w0.14: v1(162.03,115.94) 162.03,67.24 159.46,64.67 v1(159.46,56.07)
SCLK: length 125.2
  TOP w0.102: U5.AE24 137.23,80.24 137.72,79.76 ; v1(193.6,86.71) 194.16,87.27 U1.C5
  TOP w0.14: v1(192.23,81.67) 191.56,81 171.14,81 164.22,74.08 142.66,74.08 v1(139.49,77.25) 137.72,79.02 137.72,79.76
  SIG3 w0.152: v1(193.6,86.71) 193.6,83.04 v1(192.23,81.67)
  BOTTOM w0.14: J44.5 120.45,41.58 139.49,60.62 v1(139.49,77.25)
SCLK_USI: length 80.2
  TOP w0.102: v1(126.71,99.75) 126.22,99.26 U5.F13
  SIG1 w0.152: J15.5 148.42,157.47 148.42,166.51 147.16,167.76 J17.5 ; v1(126.71,99.75) 126.24,100.23 126.24,100.91 125.27,101.88 125.27,126.91 133.06,134.7 134.38,134.7 v1(145.88,146.2)
  SIG2 w0.152: v1(145.88,146.2) 145.88,154.94 J15.5
SCS: length 127.4
  TOP w0.102: 137.24,78.77 137.22,78.78 U5.AF24 ; U1.C4 v1(194.85,86.69)
  TOP w0.14: v1(192.24,80.68) 191.98,80.42 171.72,80.42 164.87,73.57 142.17,73.57 v1(138.48,77.25) 137.24,78.5 137.24,78.77
  SIG3 w0.152: v1(194.85,86.69) 194.85,82.47 193.05,80.68 v1(192.24,80.68)
  BOTTOM w0.14: v1(138.48,77.25) 138.48,61.42 117.91,40.84 J44.7
SCS1_USI: length 80.1
  TOP w0.102: v1(127.71,99.75) 127.22,99.26 U5.F14
  SIG1 w0.152: J17.3 150.93,166.52 150.93,149.63 126.21,124.92 126.21,101.8 126.95,101.07 126.95,100.52 v1(127.71,99.75)
SCS2_USI: length 67.1
  TOP w0.102: U5.F16 129.22,99.26 v1(129.72,99.75)
  SIG2 w0.152: v1(129.72,99.75) 129.72,99.76 130.2,100.24 130.2,116.11 129.45,116.85 129.45,128.16 150.93,149.63 150.93,154.96 J15.3
SDA: length 32
  TOP w0.14: J20.1 99.57,8.26 R22.1 U4.5 92.74,8.26 91.34,9.65 91.34,11.89 81.35,21.88 81.35,25.27 81.84,25.77 U2.37
SDA_FROM_CY: length 225.7
  TOP w0.14: R22.2 J20.2 R21.1 105.6,6.83 v1(105.64,6.87) ; v1(160.17,56.57) U8.12
  SIG2 w0.152: v1(147.56,125.99) 147.56,126.14 147.71,125.99 153.78,125.99 v1(162.87,116.89) ; J15.6 148.4,154.92 148.4,163.95 147.15,165.2 J17.6 ; v1(160.17,56.57) 161.28,55.47 161.28,27.2 137.86,3.79 108.72,3.79 v1(105.64,6.87)
  SIG3 w0.14: J15.6 147.15,126.4 v1(147.56,125.99)
  BOTTOM w0.14: v1(162.87,116.89) 162.87,67.1 160.17,64.4 v1(160.17,56.57)
SDI: length 131.9
  TOP w0.102: 194.86,85.44 U1.B4 ; 135.23,78.74 135.22,78.75 U5.AF22
  TOP w0.14: 194.86,85.44 194.86,80.28 194.06,79.48 183.13,79.48 176.12,72.47 141.39,72.47 v1(136.61,77.25) 135.23,78.63 135.23,78.74
  BOTTOM w0.14: v1(136.61,77.25) 137.44,76.42 137.44,63.14 126.85,52.55 125.81,52.55 115.37,42.11 J44.9
SDI_USI: length 79.5
  TOP w0.102: U5.F11 124.22,99.26 v1(124.71,99.75)
  SIG1 w0.152: v1(124.71,99.75) 124.35,99.75 123.24,100.86 123.24,130.98 143.32,151.06 143.32,154.91 J15.7 145.89,157.49 145.89,166.49 144.62,167.76 J17.7
SDO: length 129
  TOP w0.102: U1.A3 196.7,84.15 ; 131.22,78.82 U5.AF18
  TOP w0.14: 196.7,84.15 196.7,79.97 188.22,71.5 v1(140.48,71.5) 137.61,71.5 131.22,77.89 131.22,78.82
  BOTTOM w0.14: v1(140.48,71.5) 140.48,58.99 138.15,56.67 138.15,54.94 122.99,39.78 J44.3
SDO_USI: length 78.8
  TOP w0.102: U5.F12 125.22,99.26 v1(125.71,99.75)
  SIG1 w0.152: v1(125.71,99.75) 125.21,100.25 124.61,100.25 124.25,100.61 124.25,128.23 J15.4
  BOTTOM w0.14: J17.4 149.7,165.22 150.98,163.95 150.98,154.95 J15.4
SLCS_N: length 61.7
  TOP w0.102: U5.AB9 122.21,83.25 v1(121.71,82.74)
  TOP w0.14: v1(100.55,38.77) U2.92
  SIG1 w0.152: v1(121.71,82.74) 121.23,82.27 121.23,75.96 114.37,69.1 114.37,58.32 112.68,56.63 v1(112.68,39.57)
  SIG3 w0.152: v1(112.68,39.57) 111.89,38.77 v1(100.55,38.77)
SLOE: length 64.4
  TOP w0.102: 122.22,78.81 U5.AF9
  TOP w0.14: v1(121.1,71.41) 122.22,72.53 122.22,78.81
  TOP w0.152: v1(100.88,34.76) 98.99,34.76 U2.84
  SIG1 w0.152: v1(105.4,71.41) 105.4,39.28 v1(100.88,34.76)
  SIG3 w0.152: v1(121.1,71.41) v1(105.4,71.41)
SLRD: length 71.3
  TOP w0.102: 118.77,79.78 119.22,80.23 U5.AE6
  TOP w0.14: v4(90.98,42.27) 90.98,42.27 U2.4 ; 118.77,79.78 118.77,74.06 116.63,71.93 v1(116.63,44.6)
  SIG3 w0.133: v4(90.98,42.27) 94.94,42.27 97.27,44.6 109.91,44.6
  SIG3 w0.152: v1(116.63,44.6) 116.63,44.6 109.91,44.6
SLWR: length 70.4
  TOP w0.102: U5.AD6 118.75,80.77 v1(118.75,80.77)
  TOP w0.14: U2.5 v4(90.31,41.77)
  SIG1 w0.152: v1(118.75,80.77) 118.75,75.78 110.22,67.25 v1(110.22,41.77)
  SIG3 w0.152: v4(90.31,41.77) v1(110.22,41.77)
STATE0: length 59.8
  TOP w0.102: U5.AD10 123.22,81.24 v1(122.71,80.74)
  TOP w0.14: U2.108 v1(94.73,48.23)
  SIG1 w0.152: v1(122.71,80.74) 122.71,74.14 115.75,67.19 v1(115.75,48.23)
  SIG3 w0.152: v1(115.75,48.23) v1(94.73,48.23)
STATE1: length 73.2
  TOP w0.102: U5.AD17 130.22,81.23 v1(130.72,80.74)
  TOP w0.14: U2.109 v1(94.23,47.47)
  SIG1 w0.152: v1(131.72,78.74) 131.23,79.23 131.23,80.23 v1(130.72,80.74)
  SIG3 w0.152: v1(94.23,47.47) 129.58,47.47 132.51,50.4 132.51,76.61 131.72,77.4 v1(131.72,78.74)
STATE2: length 74.3
  TOP w0.102: v1(129.72,80.74) 129.22,81.23 U5.AD16
  TOP w0.14: U2.110 93.62,45.64 93.62,49.91 v1(93.76,50.06)
  SIG1 w0.152: v1(129.72,76.55) 130.22,77.06 130.22,80.23 130.22,80.23 v1(129.72,80.74)
  SIG3 w0.152: v1(93.76,50.06) 130.71,50.06 131.28,50.62 131.28,68.96 129.86,70.38 129.86,76.41 v1(129.72,76.55)
STATE3: length 62
  TOP w0.102: U5.AD11 124.22,81.24 v1(123.71,80.74)
  TOP w0.14: v1(93.21,50.77) 93.23,50.75 U2.111
  SIG3 w0.152: v1(93.21,50.77) 115.43,50.77 121.01,56.35 121.01,64.85 124.21,68.05 124.21,80.24 v1(123.71,80.74)
TCRIT1: length 54.8
  TOP w0.102: v1(128.71,81.74) 128.22,82.23 U5.AC15
  TOP w0.14: v1(130.61,74.74) 131.44,73.91 134.55,73.91 138.06,70.41 v1(158.93,70.41) ; U8.10 158.94,57.57 v1(158.93,57.56) R104.2
  SIG2 w0.152: v1(130.61,74.74) 129.21,76.15 129.21,81.25 128.72,81.74 v1(128.71,81.74)
  SIG3 w0.152: v1(158.93,57.56) v1(158.93,70.41)
TCRIT2: length 58.2
  TOP w0.102: v1(126.71,81.74) 126.22,82.23 U5.AC13
  TOP w0.14: U8.11 159.46,57.07 v1(158.45,56.06) R87.2
  SIG1 w0.152: v1(158.45,69.51) 154.49,73.47 129.8,73.47 v1(126.71,76.56)
  SIG2 w0.152: v1(126.71,76.56) 126.2,77.07 126.2,81.23 v1(126.71,81.74)
  SIG3 w0.152: v1(158.45,56.06) v1(158.45,69.51)
TCRIT3: length 58.1
  TOP w0.102: U5.AD13 126.22,81.23 v1(126.71,80.74)
  TOP w0.14: R86.2 v1(158.76,54.64) 159.7,55.57 U8.14
  SIG1 w0.152: v1(126.71,80.74) 127.23,80.23 127.23,77.43 130.72,73.94 154.99,73.94 v1(157.94,70.99)
  SIG3 w0.152: v1(157.94,70.99) 157.94,55.46 v1(158.76,54.64)
TEST1N: length 41.1
  TOP w0.102: v1(125.71,83.74) 126.22,84.24 U5.AA13 ; v1(134.55,54.18) 134.55,53.5 R30.1 134.85,52.58 134.85,49.34 134.75,49.24 U6.3
  SIG2 w0.102: v1(125.71,83.74) 125.71,83.31 125.11,82.71 125.11,70.55 128.14,67.52 128.14,61.82 134.85,55.1 134.85,54.48 v1(134.55,54.18)
TEST1P: length 40
  TOP w0.102: U5.AB13 126.22,83.25 v1(125.71,82.74) ; v1(135.35,54.18) 135.35,53.5 R30.2 135.05,52.58 135.05,49.34 135.15,49.24 U6.1
  SIG2 w0.102: v1(125.71,82.74) 125.31,82.34 125.31,70.63 128.34,67.61 128.34,61.9 135.05,55.19 135.05,54.48 v1(135.35,54.18)
TEST2N: length 37.3
  TOP w0.102: v1(129.47,54.21) 129.47,53.52 129.16,53.21 129.77,52.6 129.77,49.34 129.67,49.24 U6.7 ; U5.AA15 128.22,84.23 v1(128.71,83.74)
  SIG3 w0.102: v1(128.71,83.74) 129.11,83.34 129.11,55.61 129.77,54.95 129.77,54.51 v1(129.47,54.21)
TEST2P: length 37.3
  TOP w0.102: v1(130.27,54.21) 130.27,53.52 R39.2 129.97,52.6 129.97,49.34 130.07,49.24 U6.5 ; v1(129.72,83.74) 129.22,84.24 U5.AA16
  SIG3 w0.102: v1(130.27,54.21) 129.97,54.51 129.97,55.03 129.32,55.69 129.32,83.34 v1(129.72,83.74)
TEST3N: length 36.8
  TOP w0.102: v1(125.43,54.21) 125.43,53.52 R41.1 125.73,52.6 125.73,49.34 125.63,49.24 U7.3 ; v1(123.71,81.74) 124.22,82.25 U5.AC11
  SIG2 w0.102: v1(123.71,81.74) 124.11,81.34 124.11,70.09 127.08,67.11 127.08,57.94 125.73,56.59 125.73,54.51 v1(125.43,54.21)
TEST3P: length 36.8
  TOP w0.102: v1(124.71,81.74) 125.22,82.25 U5.AC12 ; U7.1 126.03,49.24 125.93,49.34 125.93,52.6 R41.2 126.23,53.52 v1(126.23,54.21)
  SIG2 w0.102: v1(126.23,54.21) 125.93,54.51 125.93,56.5 127.28,57.86 127.28,67.2 124.31,70.17 124.31,81.34 v1(124.71,81.74)
TEST4N: length 38.7
  TOP w0.102: v1(120.35,54.21) 120.35,53.52 R42.1 120.65,52.6 120.65,49.34 120.55,49.24 U7.7 ; v1(126.71,82.74) 127.22,83.25 U5.AB14
  SIG3 w0.102: v1(126.71,82.74) 126.71,82.74 127.11,82.34 127.11,81.91 127.11,81.91 127.11,81.57 127.11,81.57 127.11,80.91 127.11,80.91 127.11,80.57 127.11,80.57 127.11,61.38 120.62,54.9 120.62,54.49 v1(120.35,54.21)
TEST4P: length 39.8
  TOP w0.102: U7.5 120.95,49.24 120.85,49.34 120.85,52.6 R42.2 121.15,53.53 v1(121.15,54.21) ; U5.AA14 127.22,84.24 v1(126.71,83.74)
  SIG3 w0.102: v1(126.71,83.74) 126.71,83.31 127.31,82.71 127.31,82 127.31,81.99 127.31,81.49 127.31,81.48 127.31,81 127.31,80.99 127.31,80.48 127.31,80.48 127.31,61.3 127.2,61.18 127.19,61.18 120.83,54.82 120.83,54.53 v1(121.15,54.21)
TPM: length 99.3
  TOP w0.14: J4.23 157.36,144.01 R114.2
  SIG3 w0.152: J4.23 159.89,144.01 159.89,141.04 165.98,134.95 189.1,134.95 190.31,133.73 190.31,114.19 191.17,113.33 196.16,113.33 197.98,111.52 197.98,86 v1(197.32,85.35)
  BOTTOM w0.14: R8.1 197.32,85.34 v1(197.32,85.35)
TXD0: length 30.8
  TOP w0.14: U2.50 90.23,19.88 92.89,17.22 101.64,17.22 J25.2
